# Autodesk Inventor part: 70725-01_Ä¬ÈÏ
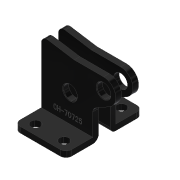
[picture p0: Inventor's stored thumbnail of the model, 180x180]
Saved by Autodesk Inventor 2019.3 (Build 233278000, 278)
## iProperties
Created: 2010-06
Part Number: 70725-01_Ä¬ÈÏ
Material: Ogólny
Document SubType Name: Modeling
Designer: CADENGINEERING4
Density: 1 g/cm^3
Appearance: Gładki — czarny
Author: CADENGINEERING4
Revision Number: ÈÎºÎ
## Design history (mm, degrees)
feature "NONE"
feature "NONE:1"
node "Bryła1"
node "Bryła2"
